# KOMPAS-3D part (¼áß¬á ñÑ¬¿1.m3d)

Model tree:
1. Эскиз:1
2. Операция выдавливания:24
     Толщина стенки 2 = 10; Расстояние 1 = 0.6
3. Эскиз:22
4. Операция выдавливания:25
     Толщина стенки 1 = 6; Толщина стенки 2 = 6; Расстояние 1 = 0.6
5. Эскиз:23
6. Операция выдавливания:26
     Толщина стенки 1 = 6; Толщина стенки 2 = 6; Расстояние 1 = 0.6
7. Эскиз:24
8. Операция выдавливания:27
     Толщина стенки 1 = 6; Толщина стенки 2 = 6; Расстояние 1 = 0.6
9. Эскиз:25
10. Вырезать элемент выдавливания:10
     Расстояние 1 = 10
